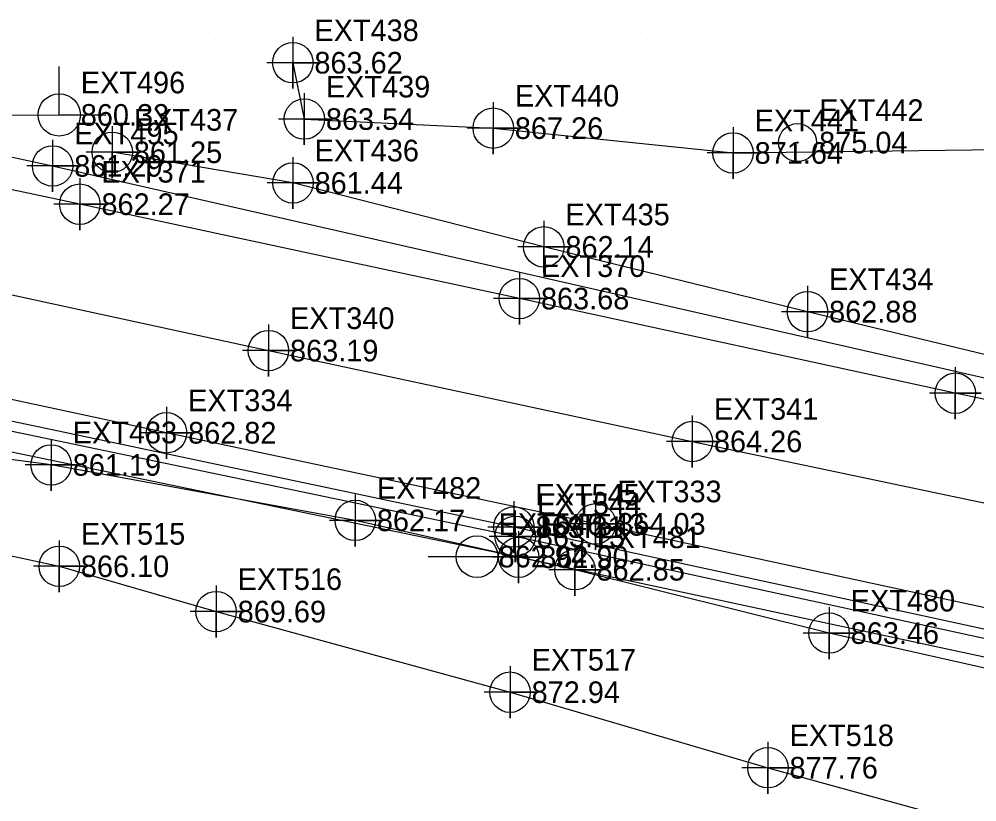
# Model space of a CAD drawing. Extents: x 1762120 to 1766775, y 709485 to 712965.
# Drawn here: x 1762238.1 to 1762348.9, y 712700.9 to 712791.5 of the extents above; entities that cross this region are included whole.
import ezdxf

# ---------------------------------------------------------------- set-up
doc = ezdxf.new("R2010")
doc.units = 0
for name, color, linetype in [('Exist DTM Breakline', 7, 'Continuous'), ('Exist DTM Breakline Cogo Elevation', 7, 'Continuous'), ('Exist DTM Breakline Cogo Number', 7, 'Continuous'), ('Exist DTM Breakline Cogo Point CELL', 7, 'Continuous'), ('Exist DTM Crownline', 7, 'Continuous'), ('Exist DTM Crownline Cogo Elevation', 7, 'Continuous'), ('Exist DTM Crownline Cogo Number', 7, 'Continuous'), ('Exist DTM Crownline Cogo Point CELL', 7, 'Continuous'), ('Exist DTM Drainline', 7, 'Continuous'), ('Exist DTM Drainline Cogo Elevation', 7, 'Continuous'), ('Exist DTM Drainline Cogo Number', 7, 'Continuous'), ('Exist DTM Drainline Cogo Point CELL', 7, 'Continuous'), ('Exist DTM QL2 LIDAR Elevation Point', 7, 'Continuous'), ('Exist Property Iron Pin CELL', 7, 'Continuous'), ('Exist Property Iron Pin Cogo Elevation', 7, 'Continuous'), ('Exist Property Iron Pin Cogo Number', 7, 'Continuous'), ('Exist Roads EOP', 7, 'Continuous'), ('Exist Roads EOP Cogo Elevation', 7, 'Continuous'), ('Exist Roads EOP Cogo Number', 7, 'Continuous'), ('Exist Roads EOP Cogo Point CELL', 7, 'Continuous'), ('Exist Utilities Gas UG Line SUE LOS C', 7, 'Continuous'), ('Exist Utilities Gas UG Line SUE LOS C Cogo Elevation', 7, 'Continuous'), ('Exist Utilities Gas UG Line SUE LOS C Cogo Number', 7, 'Continuous'), ('Exist Utilities Gas UG Line SUE LOS C Cogo Point CELL', 7, 'Continuous'), ('Exist Utilities Power Joint Use Telephone CELL', 7, 'Continuous'), ('Exist Utilities Power Joint Use Telephone Cogo Elevation', 7, 'Continuous'), ('Exist Utilities Power Joint Use Telephone Cogo Number', 7, 'Continuous'), ('Exist Utilities Telephone Pole CELL', 7, 'Continuous'), ('Exist Utilities Telephone Pole Cogo Elevation', 7, 'Continuous'), ('Exist Utilities Telephone Pole Cogo Number', 7, 'Continuous'), ('Exist Utilities Telephone UG FO SUE LOS C', 7, 'Continuous'), ('Exist Utilities Telephone UG FO SUE LOS C Cogo Elevation', 7, 'Continuous'), ('Exist Utilities Telephone UG FO SUE LOS C Cogo Number', 7, 'Continuous'), ('Exist Utilities Telephone UG FO SUE LOS C Cogo Point CELL', 7, 'Continuous'), ('Exist Utilities Water UG Line SUE LOS C', 7, 'Continuous'), ('Exist Utilities Water UG Line SUE LOS C Cogo Elevation', 7, 'Continuous'), ('Exist Utilities Water UG Line SUE LOS C Cogo Number', 7, 'Continuous'), ('Exist Utilities Water UG Line SUE LOS C Cogo Point CELL', 7, 'Continuous')]:
    doc.layers.add(name, color=color, linetype=linetype)

msp = doc.modelspace()

# ---------------------------------------------------------------- linework, layer by layer
at = {"layer": 'Exist DTM Breakline'}
for points in [[(1762269.75, 712786.47), (1762271.08, 712779.95), (1762292.95, 712778.9), (1762320.7, 712776.03), (1762354.47, 712776.48), (1762388.07, 712765.38), (1762412.81, 712762.42), (1762443.02, 712756.65), (1762473.16, 712749.14), (1762494.52, 712743.82), (1762529.01, 712735.95), (1762558.21, 712731.15), (1762590.65, 712721.47), (1762629.55, 712708.88), (1762641.1, 712705.86), (1762646.43, 712718.81), (1762637.5, 712733.74)], [(1762183.31, 712740.13), (1762222.89, 712732.5), (1762242.72, 712728.2), (1762260.87, 712722.96), (1762294.89, 712713.63), (1762324.74, 712704.89), (1762362.52, 712694.51), (1762387.62, 712687.36), (1762406.26, 712681.83), (1762438.55, 712677.19), (1762458.9, 712672.51), (1762474.39, 712669.93), (1762496.2, 712663.55), (1762513.05, 712661.01), (1762547.19, 712657.24), (1762571.69, 712653.16), (1762593.37, 712650.89), (1762601.1, 712652.92), (1762602.91, 712656.27)]]:
    msp.add_lwpolyline(points, dxfattribs=at)
at = {"layer": 'Exist DTM Breakline Cogo Point CELL'}
for points in [[(1762269.75, 712789.47), (1762269.75, 712783.47), (1762269.75, 712786.47), (1762272.75, 712786.47), (1762266.75, 712786.47)], [(1762271.08, 712782.95), (1762271.08, 712776.95), (1762271.08, 712779.95), (1762274.08, 712779.95), (1762268.08, 712779.95)], [(1762292.95, 712781.9), (1762292.95, 712775.9), (1762292.95, 712778.9), (1762295.95, 712778.9), (1762289.95, 712778.9)], [(1762320.7, 712779.03), (1762320.7, 712773.03), (1762320.7, 712776.03), (1762323.7, 712776.03), (1762317.7, 712776.03)], [(1762242.72, 712731.2), (1762242.72, 712725.2), (1762242.72, 712728.2), (1762245.72, 712728.2), (1762239.72, 712728.2)], [(1762260.87, 712725.96), (1762260.87, 712719.96), (1762260.87, 712722.96), (1762263.87, 712722.96), (1762257.87, 712722.96)], [(1762294.89, 712716.63), (1762294.89, 712710.63), (1762294.89, 712713.63), (1762297.89, 712713.63), (1762291.89, 712713.63)], [(1762324.74, 712707.89), (1762324.74, 712701.89), (1762324.74, 712704.89), (1762327.74, 712704.89), (1762321.74, 712704.89)]]:
    msp.add_lwpolyline(points, dxfattribs=at)
for centre in [(1762269.75, 712786.47), (1762271.08, 712779.95), (1762292.95, 712778.9), (1762320.7, 712776.03), (1762242.72, 712728.2), (1762260.87, 712722.96), (1762294.89, 712713.63), (1762324.74, 712704.89)]:
    msp.add_circle(centre, 2.34, dxfattribs=at)
at = {"layer": 'Exist DTM Crownline'}
msp.add_lwpolyline([(1762166.55, 712774.69), (1762217.29, 712763.93), (1762266.93, 712753.16), (1762315.99, 712742.64), (1762361.3, 712733.13), (1762409.52, 712722.71), (1762461.51, 712711.51), (1762512.12, 712700.31), (1762561, 712689.86), (1762611.48, 712678.84), (1762663.77, 712667.96), (1762715.27, 712656.97), (1762767.73, 712645.75), (1762820.16, 712634.42), (1762873.56, 712623.12), (1762907.32, 712615.87), (1762954.84, 712607.61), (1762970.66, 712604.72)], dxfattribs=at)
at = {"layer": 'Exist DTM Crownline Cogo Point CELL'}
for points in [[(1762266.93, 712756.16), (1762266.93, 712750.16), (1762266.93, 712753.16), (1762269.93, 712753.16), (1762263.93, 712753.16)], [(1762315.99, 712745.64), (1762315.99, 712739.64), (1762315.99, 712742.64), (1762318.99, 712742.64), (1762312.99, 712742.64)]]:
    msp.add_lwpolyline(points, dxfattribs=at)
for centre in [(1762266.93, 712753.16), (1762315.99, 712742.64)]:
    msp.add_circle(centre, 2.34, dxfattribs=at)
at = {"layer": 'Exist DTM Drainline'}
for points in [[(1762671.95, 712685.6), (1762648.35, 712689.78), (1762626.12, 712693.92), (1762597.99, 712699.6), (1762564.62, 712706.39), (1762531.74, 712713.3), (1762498.47, 712720.2), (1762464.8, 712728.4), (1762431.89, 712735.46), (1762397.08, 712742.59), (1762358.77, 712750.54), (1762329.32, 712757.66), (1762298.8, 712765.16), (1762269.77, 712772.56), (1762248.85, 712776.11)], [(1762607.34, 712658.7), (1762593.44, 712665.01), (1762568.56, 712671.1), (1762531.51, 712678.41), (1762506.12, 712683.06), (1762483.93, 712688.33), (1762453.21, 712695.91), (1762419.5, 712702.24), (1762383.47, 712709.67), (1762355.69, 712715.12), (1762331.82, 712720.47), (1762302.4, 712727.8), (1762276.98, 712733.51), (1762241.78, 712739.93), (1762203.56, 712744.94), (1762183.53, 712748.07)]]:
    msp.add_lwpolyline(points, dxfattribs=at)
at = {"layer": 'Exist DTM Drainline Cogo Point CELL'}
for points in [[(1762248.85, 712779.11), (1762248.85, 712773.11), (1762248.85, 712776.11), (1762251.85, 712776.11), (1762245.85, 712776.11)], [(1762269.77, 712775.56), (1762269.77, 712769.56), (1762269.77, 712772.56), (1762272.77, 712772.56), (1762266.77, 712772.56)], [(1762298.8, 712768.16), (1762298.8, 712762.16), (1762298.8, 712765.16), (1762301.8, 712765.16), (1762295.8, 712765.16)], [(1762329.32, 712760.66), (1762329.32, 712754.66), (1762329.32, 712757.66), (1762332.32, 712757.66), (1762326.32, 712757.66)], [(1762241.78, 712742.93), (1762241.78, 712736.93), (1762241.78, 712739.93), (1762244.78, 712739.93), (1762238.78, 712739.93)], [(1762276.98, 712736.51), (1762276.98, 712730.51), (1762276.98, 712733.51), (1762279.98, 712733.51), (1762273.98, 712733.51)], [(1762302.4, 712730.8), (1762302.4, 712724.8), (1762302.4, 712727.8), (1762305.4, 712727.8), (1762299.4, 712727.8)], [(1762331.82, 712723.47), (1762331.82, 712717.47), (1762331.82, 712720.47), (1762334.82, 712720.47), (1762328.82, 712720.47)]]:
    msp.add_lwpolyline(points, dxfattribs=at)
for centre in [(1762248.85, 712776.11), (1762269.77, 712772.56), (1762298.8, 712765.16), (1762329.32, 712757.66), (1762241.78, 712739.93), (1762276.98, 712733.51), (1762302.4, 712727.8), (1762331.82, 712720.47)]:
    msp.add_circle(centre, 2.34, dxfattribs=at)
at = {"layer": 'Exist DTM QL2 LIDAR Elevation Point'}
for p, q in [((1762240, 712790), (1762240, 712790)), ((1762250, 712790), (1762250, 712790)), ((1762260, 712790), (1762260, 712790)), ((1762270, 712790), (1762270, 712790)), ((1762280, 712790), (1762280, 712790)), ((1762290, 712790), (1762290, 712790)), ((1762300, 712790), (1762300, 712790)), ((1762310, 712790), (1762310, 712790)), ((1762320, 712790), (1762320, 712790)), ((1762330, 712790), (1762330, 712790)), ((1762340, 712790), (1762340, 712790)), ((1762240, 712780), (1762240, 712780)), ((1762250, 712780), (1762250, 712780)), ((1762300, 712780), (1762300, 712780)), ((1762310, 712780), (1762310, 712780)), ((1762320, 712780), (1762320, 712780)), ((1762330, 712780), (1762330, 712780)), ((1762340, 712780), (1762340, 712780)), ((1762240, 712720), (1762240, 712720)), ((1762250, 712720), (1762250, 712720)), ((1762260, 712720), (1762260, 712720)), ((1762240, 712710), (1762240, 712710)), ((1762250, 712710), (1762250, 712710)), ((1762260, 712710), (1762260, 712710)), ((1762270, 712710), (1762270, 712710)), ((1762280, 712710), (1762280, 712710)), ((1762290, 712710), (1762290, 712710))]:
    msp.add_line(p, q, dxfattribs=at)
at = {"layer": 'Exist Property Iron Pin CELL'}
for radius in [2.2, 0.0707]:
    msp.add_circle((1762328.17, 712777.23), radius, dxfattribs=at)
at = {"layer": 'Exist Roads EOP'}
for points in [[(1762972.64, 712616.33), (1762930.48, 712622.91), (1762881.99, 712633.2), (1762831.97, 712644.06), (1762782.82, 712654.41), (1762735.74, 712664.41), (1762686.68, 712675.53), (1762639.56, 712685.27), (1762589.4, 712696.15), (1762546.23, 712705.49), (1762496.4, 712716.08), (1762446.15, 712726.9), (1762396.23, 712737.69), (1762346.43, 712748.23), (1762295.97, 712759.18), (1762245.1, 712770.1), (1762193.68, 712780.97), (1762169, 712786.42)], [(1762974.58, 712585.31), (1762927.98, 712597.84), (1762890.67, 712606.3), (1762842.51, 712617.09), (1762793.23, 712628.15), (1762744.7, 712638.79), (1762696.33, 712649.07), (1762645.67, 712659.58), (1762597.31, 712669.97), (1762548.88, 712680.54), (1762499.87, 712691.04), (1762451.78, 712701.31), (1762402.08, 712712.16), (1762353.64, 712722.59), (1762304.8, 712733.11), (1762255.13, 712743.65), (1762207.34, 712753.91), (1762164.28, 712763.06), (1762150.69, 712765.78)]]:
    msp.add_lwpolyline(points, dxfattribs=at)
at = {"layer": 'Exist Roads EOP Cogo Point CELL'}
for points in [[(1762245.1, 712773.1), (1762245.1, 712767.1), (1762245.1, 712770.1), (1762248.1, 712770.1), (1762242.1, 712770.1)], [(1762295.97, 712762.18), (1762295.97, 712756.18), (1762295.97, 712759.18), (1762298.97, 712759.18), (1762292.97, 712759.18)], [(1762346.43, 712751.23), (1762346.43, 712745.23), (1762346.43, 712748.23), (1762349.43, 712748.23), (1762343.43, 712748.23)], [(1762255.13, 712746.65), (1762255.13, 712740.65), (1762255.13, 712743.65), (1762258.13, 712743.65), (1762252.13, 712743.65)], [(1762304.8, 712736.11), (1762304.8, 712730.11), (1762304.8, 712733.11), (1762307.8, 712733.11), (1762301.8, 712733.11)]]:
    msp.add_lwpolyline(points, dxfattribs=at)
for centre in [(1762245.1, 712770.1), (1762295.97, 712759.18), (1762346.43, 712748.23), (1762255.13, 712743.65), (1762304.8, 712733.11)]:
    msp.add_circle(centre, 2.34, dxfattribs=at)
at = {"layer": 'Exist Utilities Gas UG Line SUE LOS C'}
msp.add_lwpolyline([(1762186.21, 712786.58), (1762241.95, 712774.53), (1762368.98, 712745.66), (1762446.66, 712730.32), (1762499.18, 712718.67), (1762560.33, 712705.06), (1762614.27, 712693.34), (1762654.57, 712685.66), (1762695.77, 712676.76), (1762747.57, 712665.85), (1762826.12, 712649.31), (1762887.98, 712636.74)], dxfattribs=at)
at = {"layer": 'Exist Utilities Gas UG Line SUE LOS C Cogo Point CELL'}
msp.add_lwpolyline([(1762241.95, 712777.53), (1762241.95, 712771.53), (1762241.95, 712774.53), (1762244.95, 712774.53), (1762238.95, 712774.53)], dxfattribs=at)
msp.add_circle((1762241.95, 712774.53), 2.34, dxfattribs=at)
at = {"layer": 'Exist Utilities Power Joint Use Telephone CELL'}
msp.add_line((1762242.71, 712780.43), (1762242.71, 712780.43), dxfattribs=at)
msp.add_lwpolyline([(1762236.77, 712780.43), (1762248.1, 712780.39), (1762242.71, 712780.41), (1762242.71, 712786.05)], dxfattribs=at)
msp.add_circle((1762242.71, 712780.43), 2.45, dxfattribs=at)
at = {"layer": 'Exist Utilities Telephone Pole CELL'}
for p, q in [((1762285.4, 712729.32), (1762296.73, 712729.32)), ((1762291.07, 712729.32), (1762291.07, 712729.32))]:
    msp.add_line(p, q, dxfattribs=at)
msp.add_circle((1762291.07, 712729.32), 2.41, dxfattribs=at)
at = {"layer": 'Exist Utilities Telephone UG FO SUE LOS C'}
for points in [[(1762655.15, 712653.25), (1762586.52, 712669.54), (1762459.67, 712695.94), (1762295.49, 712731.66), (1762171.26, 712757.55)], [(1762655.08, 712650.85), (1762586.39, 712667.09), (1762459.96, 712694.03), (1762295.89, 712729.25), (1762171.95, 712754.92)]]:
    msp.add_lwpolyline(points, dxfattribs=at)
at = {"layer": 'Exist Utilities Telephone UG FO SUE LOS C Cogo Point CELL'}
for points in [[(1762295.49, 712734.66), (1762295.49, 712728.66), (1762295.49, 712731.66), (1762298.49, 712731.66), (1762292.49, 712731.66)], [(1762295.89, 712732.25), (1762295.89, 712726.25), (1762295.89, 712729.25), (1762298.89, 712729.25), (1762292.89, 712729.25)]]:
    msp.add_lwpolyline(points, dxfattribs=at)
for centre in [(1762295.49, 712731.66), (1762295.89, 712729.25)]:
    msp.add_circle(centre, 2.34, dxfattribs=at)
at = {"layer": 'Exist Utilities Water UG Line SUE LOS C'}
msp.add_lwpolyline([(1762652.6, 712655.88), (1762584.51, 712671.06), (1762460.33, 712696.95), (1762295.33, 712732.74), (1762171.02, 712758.92)], dxfattribs=at)
at = {"layer": 'Exist Utilities Water UG Line SUE LOS C Cogo Point CELL'}
msp.add_lwpolyline([(1762295.33, 712735.74), (1762295.33, 712729.74), (1762295.33, 712732.74), (1762298.33, 712732.74), (1762292.33, 712732.74)], dxfattribs=at)
msp.add_circle((1762295.33, 712732.74), 2.34, dxfattribs=at)

# ---------------------------------------------------------------- texts
at = {"layer": 'Exist DTM Breakline Cogo Elevation'}
for s, p in [('863.62', (1762272.25, 712785.22)), ('863.54', (1762273.58, 712778.7)), ('867.26', (1762295.45, 712777.65)), ('871.64', (1762323.2, 712774.78)), ('866.10', (1762245.22, 712726.95)), ('869.69', (1762263.37, 712721.71)), ('872.94', (1762297.39, 712712.38)), ('877.76', (1762327.24, 712703.64))]:
    msp.add_text(s, height=2.5, dxfattribs=at).set_placement(p)
at = {"layer": 'Exist DTM Breakline Cogo Number'}
for s, p in [('EXT438', (1762272.25, 712788.97)), ('EXT439', (1762273.58, 712782.45)), ('EXT440', (1762295.45, 712781.4)), ('EXT441', (1762323.2, 712778.53)), ('EXT515', (1762245.22, 712730.7)), ('EXT516', (1762263.37, 712725.46)), ('EXT517', (1762297.39, 712716.13)), ('EXT518', (1762327.24, 712707.39))]:
    msp.add_text(s, height=2.5, dxfattribs=at).set_placement(p)
at = {"layer": 'Exist DTM Crownline Cogo Elevation'}
for s, p in [('863.19', (1762269.43, 712751.91)), ('864.26', (1762318.49, 712741.4))]:
    msp.add_text(s, height=2.5, dxfattribs=at).set_placement(p)
at = {"layer": 'Exist DTM Crownline Cogo Number'}
for s, p in [('EXT340', (1762269.43, 712755.66)), ('EXT341', (1762318.49, 712745.15))]:
    msp.add_text(s, height=2.5, dxfattribs=at).set_placement(p)
at = {"layer": 'Exist DTM Drainline Cogo Elevation'}
for s, p in [('861.25', (1762251.35, 712774.86)), ('861.44', (1762272.27, 712771.31)), ('862.14', (1762301.3, 712763.91)), ('862.88', (1762331.82, 712756.41)), ('861.19', (1762244.28, 712738.68)), ('862.17', (1762279.48, 712732.26)), ('862.85', (1762304.9, 712726.55)), ('863.46', (1762334.32, 712719.22))]:
    msp.add_text(s, height=2.5, dxfattribs=at).set_placement(p)
at = {"layer": 'Exist DTM Drainline Cogo Number'}
for s, p in [('EXT437', (1762251.35, 712778.61)), ('EXT436', (1762272.27, 712775.06)), ('EXT435', (1762301.3, 712767.66)), ('EXT434', (1762331.82, 712760.16)), ('EXT483', (1762244.28, 712742.43)), ('EXT482', (1762279.48, 712736.01)), ('EXT481', (1762304.9, 712730.3)), ('EXT480', (1762334.32, 712722.97))]:
    msp.add_text(s, height=2.5, dxfattribs=at).set_placement(p)
at = {"layer": 'Exist Property Iron Pin Cogo Elevation'}
msp.add_text('875.04', height=2.5, dxfattribs=at).set_placement((1762330.67, 712775.98))
at = {"layer": 'Exist Property Iron Pin Cogo Number'}
msp.add_text('EXT442', height=2.5, dxfattribs=at).set_placement((1762330.67, 712779.73))
at = {"layer": 'Exist Roads EOP Cogo Elevation'}
for s, p in [('862.27', (1762247.6, 712768.85)), ('863.68', (1762298.47, 712757.93)), ('862.82', (1762257.63, 712742.4)), ('864.03', (1762307.3, 712731.86))]:
    msp.add_text(s, height=2.5, dxfattribs=at).set_placement(p)
at = {"layer": 'Exist Roads EOP Cogo Number'}
for s, p in [('EXT371', (1762247.6, 712772.6)), ('EXT370', (1762298.47, 712761.68)), ('EXT334', (1762257.63, 712746.15)), ('EXT333', (1762307.3, 712735.61))]:
    msp.add_text(s, height=2.5, dxfattribs=at).set_placement(p)
at = {"layer": 'Exist Utilities Gas UG Line SUE LOS C Cogo Elevation'}
msp.add_text('861.29', height=2.5, dxfattribs=at).set_placement((1762244.45, 712773.28))
at = {"layer": 'Exist Utilities Gas UG Line SUE LOS C Cogo Number'}
msp.add_text('EXT495', height=2.5, dxfattribs=at).set_placement((1762244.45, 712777.03))
at = {"layer": 'Exist Utilities Power Joint Use Telephone Cogo Elevation'}
msp.add_text('860.33', height=2.5, dxfattribs=at).set_placement((1762245.21, 712779.18))
at = {"layer": 'Exist Utilities Power Joint Use Telephone Cogo Number'}
msp.add_text('EXT496', height=2.5, dxfattribs=at).set_placement((1762245.21, 712782.93))
at = {"layer": 'Exist Utilities Telephone Pole Cogo Elevation'}
msp.add_text('862.94', height=2.5, dxfattribs=at).set_placement((1762293.57, 712728.07))
at = {"layer": 'Exist Utilities Telephone Pole Cogo Number'}
msp.add_text('EXT546', height=2.5, dxfattribs=at).set_placement((1762293.57, 712731.82))
at = {"layer": 'Exist Utilities Telephone UG FO SUE LOS C Cogo Elevation'}
for s, p in [('863.13', (1762297.99, 712730.41)), ('862.90', (1762298.39, 712728))]:
    msp.add_text(s, height=2.5, dxfattribs=at).set_placement(p)
at = {"layer": 'Exist Utilities Telephone UG FO SUE LOS C Cogo Number'}
for s, p in [('EXT544', (1762297.99, 712734.16)), ('EXT543', (1762298.39, 712731.75))]:
    msp.add_text(s, height=2.5, dxfattribs=at).set_placement(p)
at = {"layer": 'Exist Utilities Water UG Line SUE LOS C Cogo Elevation'}
msp.add_text('863.31', height=2.5, dxfattribs=at).set_placement((1762297.83, 712731.49))
at = {"layer": 'Exist Utilities Water UG Line SUE LOS C Cogo Number'}
msp.add_text('EXT545', height=2.5, dxfattribs=at).set_placement((1762297.83, 712735.24))

doc.saveas('drawing.dxf')
